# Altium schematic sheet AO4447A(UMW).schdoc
size 127 x 101 mm
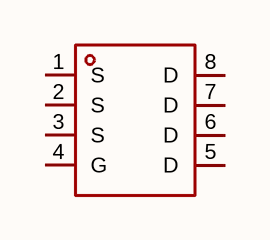
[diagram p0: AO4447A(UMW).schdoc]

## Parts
Q?  ao4447a(umw)  [SOP-8_L4.9-W3.9-P1.27-LS6.0-BL]  (value not drawn)

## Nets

Not connected (* = marked no-connect by the designer): Q? 1(S) 2(S) 3(S) 4(G) 5(D) 6(D) 7(D) 8(D)

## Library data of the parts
Q? = ao4447a(umw): 漏源电压(Vdss):30V;连续漏极电流(Id):18.5A;导通电阻(RDS(on)):4.7mΩ@10V；6.3mΩ@4.5V;耗散功率(Pd):3.1W;阈值电压(Vgs(th)):1.7V@250uA;; Manufacturer: UMW(友台半导体); AddInBom: yes; ModelId: 75c24a7891ee4dd6bdac16a7163ff87e; ModelName: SOP-8_L4.9-W3.9-P1.27-LS6.0-BL-1; ModelTransform: 192.913,236.22,0,0,0,0,-0.393,2.749,0; Drain to Source Voltage: 30V; Current - Continuous Drain(Id): 18.5A; Pd - Power Dissipation: 3.1W; Gate Charge(Qg): 93nC@10V; Input Capacitance(Ciss): 5.02nF; Reverse Transfer Capacitance (Crss@Vds): 615pF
